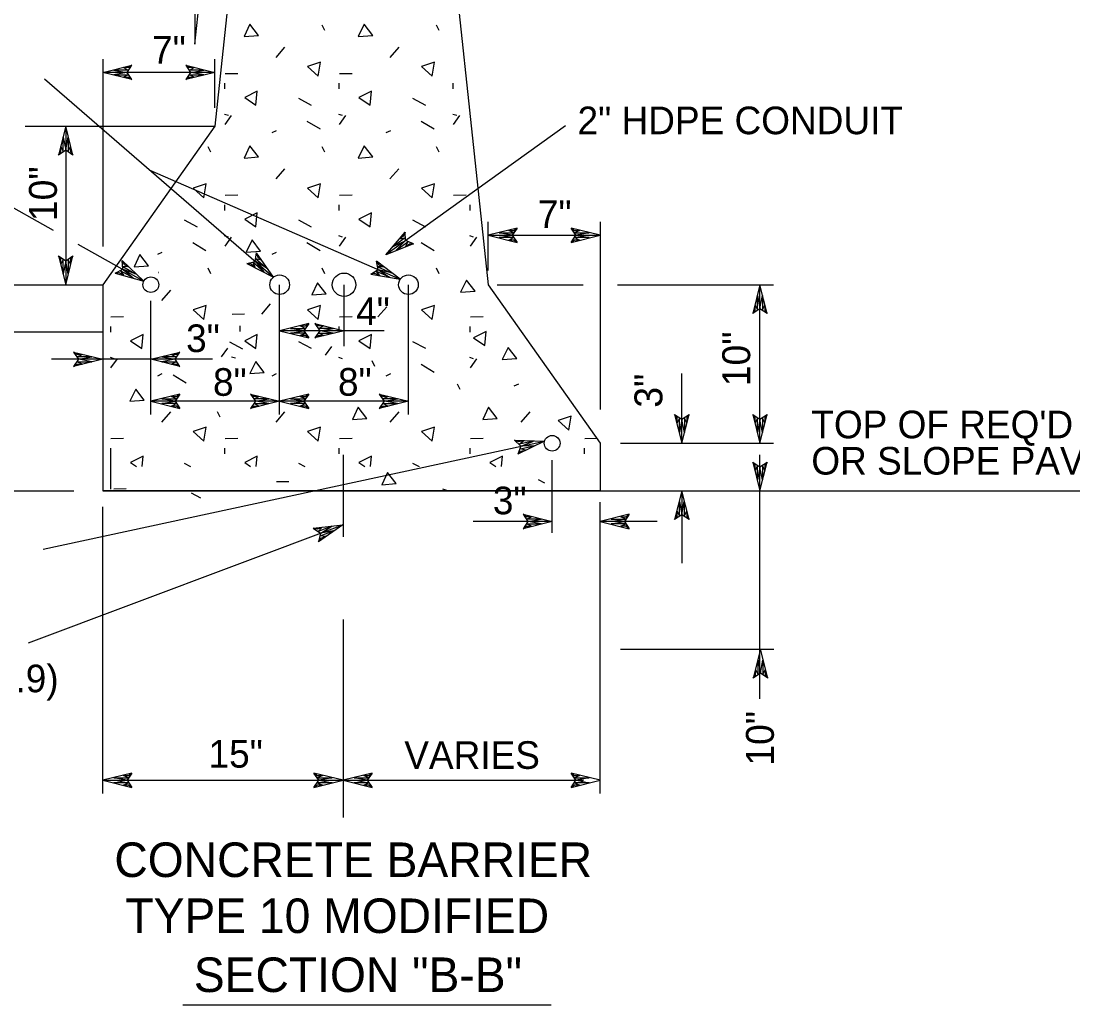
# Model space of a CAD drawing. Extents: x 504255 to 505955, y 659986 to 661086.
# Drawn here: x 504800.9 to 505019.2, y 660598.4 to 660802.7 of the extents above; entities that cross this region are included whole.
import ezdxf

# ---------------------------------------------------------------- set-up
doc = ezdxf.new("R2010")
doc.units = 0
for name, color, linetype in [('Level1', 7, 'Continuous'), ('Level3', 7, 'Continuous'), ('Level63', 7, 'Continuous')]:
    doc.layers.add(name, color=color, linetype=linetype)

msp = doc.modelspace()

# ---------------------------------------------------------------- linework, layer by layer
at = {"layer": 'Level1'}
for p, q in [((504836.94, 660797.95), (504841, 660836.25)), ((504836.94, 660836.25), (504836.94, 660797.95)), ((504817.81, 660794.84), (504817.81, 660755.89)), ((504841.09, 660784.74), (504841.09, 660794.84)), ((504841.09, 660792.07), (504817.81, 660792.07)), ((504805.69, 660790.75), (504853.25, 660749.56)), ((504801.72, 660780.9), (504841.09, 660780.9)), ((504810.12, 660780.9), (504810.12, 660747.99)), ((504913.88, 660780.98), (504876.56, 660754.22)), ((504827.59, 660771.79), (504879.56, 660749.11)), ((504792.67, 660767.62), (504807.54, 660759.29)), ((504897.78, 660750.93), (504897.78, 660761.02)), ((504921.05, 660761.02), (504921.05, 660722.07)), ((504812.63, 660756.44), (504826.35, 660748.74)), ((504897.78, 660758.26), (504921.05, 660758.26)), ((504795.68, 660747.99), (504817.81, 660747.99)), ((504854.52, 660721.03), (504854.52, 660747.99)), ((504867.88, 660735.21), (504867.88, 660747.99)), ((504881.25, 660721.03), (504881.25, 660747.99)), ((504899.7, 660747.99), (504917.49, 660747.99)), ((504924.66, 660747.99), (504957, 660747.99)), ((504954.2, 660715.08), (504954.2, 660747.99)), ((504827.79, 660721.03), (504827.79, 660744.66)), ((504876.24, 660738.42), (504854.52, 660738.42)), ((504840.61, 660732.51), (504807.19, 660732.51)), ((504938.01, 660715.08), (504938.01, 660729.53)), ((504854.52, 660723.79), (504827.79, 660723.79)), ((504881.25, 660723.79), (504854.52, 660723.79)), ((504805.43, 660693.05), (504909.51, 660715.51)), ((504925.29, 660715.08), (504957, 660715.08)), ((504867.68, 660712.65), (504867.68, 660695.64)), ((504911.08, 660696.5), (504911.08, 660711.53)), ((504954.2, 660662), (504954.2, 660712.65)), ((504768.57, 660705.2), (504811.82, 660705.2)), ((504938.01, 660705.2), (504938.01, 660690.18)), ((504817.81, 660642.32), (504817.81, 660701.86)), ((504921.05, 660642.32), (504921.05, 660702.87)), ((504802.41, 660673.61), (504867.67, 660698.15)), ((504911.08, 660698.82), (504894.72, 660698.82)), ((504932.88, 660698.82), (504921.05, 660698.82)), ((504867.69, 660678.46), (504867.69, 660637.37)), ((504925.29, 660672.29), (504957.1, 660672.29)), ((504817.81, 660645.08), (504867.69, 660645.08)), ((504867.69, 660645.08), (504917.56, 660645.08)), ((504834.41, 660598.43), (504910.91, 660598.43))]:
    msp.add_line(p, q, dxfattribs=at)
for points in [[(504847.43, 660840.63), (504841.09, 660780.9)], [(504887.94, 660840.63), (504897.78, 660747.99)], [(504823.85, 660790.58), (504817.81, 660792.07), (504823.85, 660793.57), (504823.14, 660793.07), (504822.09, 660793.07), (504823.1, 660792.57), (504820.08, 660792.57), (504822.77, 660792.07), (504820.08, 660791.57), (504823.1, 660791.57), (504822.09, 660791.08), (504823.14, 660791.08), (504823.85, 660790.58), (504822.85, 660792.07), (504823.85, 660793.57)], [(504835.04, 660793.57), (504841.09, 660792.07), (504835.04, 660790.58), (504835.76, 660791.08), (504836.8, 660791.08), (504835.79, 660791.57), (504838.81, 660791.57), (504836.13, 660792.07), (504838.81, 660792.57), (504835.79, 660792.57), (504836.8, 660793.07), (504835.76, 660793.07), (504835.04, 660793.57), (504836.05, 660792.07), (504835.04, 660790.58)], [(504811.63, 660774.92), (504810.12, 660780.9), (504808.61, 660774.92), (504809.12, 660775.63), (504809.12, 660776.67), (504809.62, 660775.67), (504809.62, 660778.66), (504810.12, 660776), (504810.62, 660778.66), (504810.62, 660775.67), (504811.13, 660776.67), (504811.13, 660775.63), (504811.63, 660774.92), (504810.12, 660775.92), (504808.61, 660774.92)], [(504841.09, 660780.9), (504817.81, 660747.99)], [(504882.32, 660756.51), (504876.56, 660754.22), (504880.56, 660758.93), (504880.27, 660758.11), (504879.43, 660757.51), (504880.55, 660757.69), (504878.1, 660755.93), (504880.57, 660757.1), (504878.68, 660755.13), (504881.14, 660756.89), (504880.61, 660755.89), (504881.45, 660756.51), (504882.32, 660756.51), (504880.63, 660757.14), (504880.56, 660758.93)], [(504903.82, 660759.75), (504897.78, 660758.26), (504903.82, 660756.77), (504903.11, 660757.26), (504902.06, 660757.26), (504903.07, 660757.76), (504900.05, 660757.76), (504902.74, 660758.26), (504900.05, 660758.75), (504903.07, 660758.75), (504902.06, 660759.26), (504903.11, 660759.26), (504903.82, 660759.75), (504902.81, 660758.26), (504903.82, 660756.77)], [(504915.02, 660756.77), (504921.05, 660758.26), (504915.02, 660759.75), (504915.73, 660759.26), (504916.77, 660759.26), (504915.76, 660758.75), (504918.78, 660758.75), (504916.1, 660758.26), (504918.78, 660757.76), (504915.76, 660757.76), (504916.77, 660757.26), (504915.73, 660757.26), (504915.02, 660756.77), (504916.02, 660758.26), (504915.02, 660759.75)], [(504847.72, 660752.37), (504853.25, 660749.56), (504849.7, 660754.62), (504849.91, 660753.78), (504850.69, 660753.1), (504849.6, 660753.38), (504851.88, 660751.41), (504849.52, 660752.79), (504851.22, 660750.66), (504848.94, 660752.64), (504849.37, 660751.6), (504848.59, 660752.28), (504847.72, 660752.37), (504849.47, 660752.84), (504849.7, 660754.62)], [(504808.61, 660753.97), (504810.12, 660747.99), (504811.63, 660753.97), (504811.13, 660753.26), (504811.13, 660752.23), (504810.63, 660753.23), (504810.63, 660750.24), (504810.12, 660752.9), (504809.62, 660750.24), (504809.62, 660753.23), (504809.12, 660752.23), (504809.12, 660753.26), (504808.61, 660753.97), (504810.12, 660752.97), (504811.63, 660753.97)], [(504820.36, 660750.39), (504826.35, 660748.74), (504821.84, 660752.99), (504822.22, 660752.21), (504823.12, 660751.7), (504822, 660751.76), (504824.62, 660750.28), (504822.04, 660751.16), (504824.14, 660749.42), (504821.5, 660750.89), (504822.13, 660749.96), (504821.23, 660750.48), (504820.36, 660750.39), (504821.98, 660751.2), (504821.84, 660752.99)], [(504873.44, 660750.16), (504879.56, 660749.11), (504874.65, 660752.89), (504875.1, 660752.15), (504876.05, 660751.73), (504874.92, 660751.68), (504877.69, 660750.47), (504875.03, 660751.09), (504877.29, 660749.56), (504874.52, 660750.77), (504875.24, 660749.91), (504874.29, 660750.33), (504873.44, 660750.16), (504874.96, 660751.13), (504874.65, 660752.89)], [(504817.81, 660747.99), (504817.81, 660705.2)], [(504897.78, 660747.99), (504921.05, 660715.08)], [(504955.71, 660742.01), (504954.2, 660747.99), (504952.7, 660742.01), (504953.2, 660742.72), (504953.2, 660743.75), (504953.7, 660742.75), (504953.7, 660745.75), (504954.2, 660743.08), (504954.71, 660745.75), (504954.71, 660742.75), (504955.21, 660743.75), (504955.21, 660742.72), (504955.71, 660742.01), (504954.2, 660743.01), (504952.7, 660742.01)], [(504860.56, 660739.92), (504854.52, 660738.42), (504860.56, 660736.93), (504859.85, 660737.43), (504858.8, 660737.43), (504859.81, 660737.93), (504856.79, 660737.93), (504859.47, 660738.42), (504856.79, 660738.92), (504859.81, 660738.92), (504858.8, 660739.42), (504859.85, 660739.42), (504860.56, 660739.92), (504859.55, 660738.42), (504860.56, 660736.93)], [(504861.84, 660739.92), (504867.88, 660738.42), (504861.84, 660736.93), (504862.56, 660737.43), (504863.6, 660737.43), (504862.59, 660737.93), (504865.61, 660737.93), (504862.93, 660738.42), (504865.61, 660738.92), (504862.59, 660738.92), (504863.6, 660739.42), (504862.56, 660739.42), (504861.84, 660739.92), (504862.85, 660738.42), (504861.84, 660736.93)], [(504811.77, 660734), (504817.81, 660732.51), (504811.77, 660731.02), (504812.49, 660731.51), (504813.53, 660731.51), (504812.52, 660732.01), (504815.54, 660732.01), (504812.86, 660732.51), (504815.54, 660733.01), (504812.52, 660733.01), (504813.53, 660733.51), (504812.49, 660733.51), (504811.77, 660734), (504812.78, 660732.51), (504811.77, 660731.02)], [(504833.82, 660731.02), (504827.79, 660732.51), (504833.82, 660734), (504833.11, 660733.51), (504832.07, 660733.51), (504833.08, 660733.01), (504830.06, 660733.01), (504832.74, 660732.51), (504830.06, 660732.01), (504833.08, 660732.01), (504832.07, 660731.51), (504833.11, 660731.51), (504833.82, 660731.02), (504832.82, 660732.51), (504833.82, 660734)], [(504833.83, 660725.29), (504827.79, 660723.79), (504833.83, 660722.3), (504833.11, 660722.8), (504832.07, 660722.8), (504833.08, 660723.3), (504830.06, 660723.3), (504832.74, 660723.79), (504830.06, 660724.29), (504833.08, 660724.29), (504832.07, 660724.79), (504833.11, 660724.79), (504833.83, 660725.29), (504832.82, 660723.79), (504833.83, 660722.3)], [(504848.48, 660725.29), (504854.52, 660723.79), (504848.48, 660722.3), (504849.19, 660722.8), (504850.23, 660722.8), (504849.23, 660723.3), (504852.25, 660723.3), (504849.57, 660723.79), (504852.25, 660724.29), (504849.23, 660724.29), (504850.23, 660724.79), (504849.19, 660724.79), (504848.48, 660725.29), (504849.49, 660723.79), (504848.48, 660722.3)], [(504860.56, 660725.29), (504854.52, 660723.79), (504860.56, 660722.3), (504859.85, 660722.8), (504858.8, 660722.8), (504859.81, 660723.3), (504856.79, 660723.3), (504859.47, 660723.79), (504856.79, 660724.29), (504859.81, 660724.29), (504858.8, 660724.79), (504859.85, 660724.79), (504860.56, 660725.29), (504859.55, 660723.79), (504860.56, 660722.3)], [(504875.21, 660725.29), (504881.25, 660723.79), (504875.21, 660722.3), (504875.92, 660722.8), (504876.97, 660722.8), (504875.96, 660723.3), (504878.98, 660723.3), (504876.3, 660723.79), (504878.98, 660724.29), (504875.96, 660724.29), (504876.97, 660724.79), (504875.92, 660724.79), (504875.21, 660725.29), (504876.22, 660723.79), (504875.21, 660722.3)], [(504936.5, 660721.05), (504938.01, 660715.08), (504939.52, 660721.05), (504939.02, 660720.35), (504939.02, 660719.32), (504938.52, 660720.31), (504938.52, 660717.33), (504938.01, 660719.98), (504937.51, 660717.33), (504937.51, 660720.31), (504937.01, 660719.32), (504937.01, 660720.35), (504936.5, 660721.05), (504938.01, 660720.06), (504939.52, 660721.05)], [(504952.7, 660721.04), (504954.2, 660715.08), (504955.71, 660721.04), (504955.21, 660720.34), (504955.21, 660719.31), (504954.71, 660720.31), (504954.71, 660717.32), (504954.2, 660719.98), (504953.7, 660717.32), (504953.7, 660720.31), (504953.2, 660719.31), (504953.2, 660720.34), (504952.7, 660721.04), (504954.2, 660720.05), (504955.71, 660721.04)], [(504903.3, 660715.7), (504909.51, 660715.51), (504903.94, 660712.78), (504904.53, 660713.42), (504905.54, 660713.64), (504904.45, 660713.91), (504907.4, 660714.56), (504904.67, 660714.47), (504907.19, 660715.52), (504904.24, 660714.88), (504905.12, 660715.59), (504904.1, 660715.36), (504903.3, 660715.7), (504904.6, 660714.45), (504903.94, 660712.78)], [(504921.05, 660715.08), (504921.05, 660705.2)], [(504952.7, 660711.17), (504954.2, 660705.2), (504955.71, 660711.17), (504955.21, 660710.47), (504955.21, 660709.44), (504954.71, 660710.44), (504954.71, 660707.45), (504954.2, 660710.11), (504953.7, 660707.45), (504953.7, 660710.44), (504953.2, 660709.44), (504953.2, 660710.47), (504952.7, 660711.17), (504954.2, 660710.18), (504955.71, 660711.17)], [(504921.05, 660705.2), (504817.81, 660705.2)], [(504939.52, 660699.23), (504938.01, 660705.2), (504936.5, 660699.23), (504937.01, 660699.93), (504937.01, 660700.96), (504937.51, 660699.96), (504937.51, 660702.96), (504938.01, 660700.29), (504938.51, 660702.96), (504938.51, 660699.96), (504939.02, 660700.96), (504939.02, 660699.93), (504939.52, 660699.23), (504938.01, 660700.22), (504936.5, 660699.23)], [(504905.04, 660700.32), (504911.08, 660698.82), (504905.04, 660697.33), (504905.75, 660697.83), (504906.79, 660697.83), (504905.79, 660698.33), (504908.8, 660698.33), (504906.12, 660698.82), (504908.8, 660699.32), (504905.79, 660699.32), (504906.79, 660699.82), (504905.75, 660699.82), (504905.04, 660700.32), (504906.05, 660698.82), (504905.04, 660697.33)], [(504927.09, 660700.32), (504921.05, 660698.82), (504927.09, 660697.33), (504926.38, 660697.83), (504925.34, 660697.83), (504926.34, 660698.33), (504923.32, 660698.33), (504926.01, 660698.82), (504923.32, 660699.32), (504926.34, 660699.32), (504925.34, 660699.82), (504926.38, 660699.82), (504927.09, 660700.32), (504926.08, 660698.82), (504927.09, 660697.33)], [(504861.49, 660697.43), (504867.67, 660698.15), (504862.56, 660694.63), (504863.05, 660695.35), (504864.02, 660695.72), (504862.9, 660695.83), (504865.72, 660696.9), (504863.04, 660696.41), (504865.38, 660697.82), (504862.55, 660696.76), (504863.31, 660697.58), (504862.34, 660697.21), (504861.49, 660697.43), (504862.97, 660696.38), (504862.56, 660694.63)], [(504955.82, 660666.31), (504954.31, 660672.29), (504952.8, 660666.31), (504953.31, 660667.01), (504953.31, 660668.05), (504953.81, 660667.05), (504953.81, 660670.04), (504954.31, 660667.38), (504954.81, 660670.04), (504954.81, 660667.05), (504955.31, 660668.05), (504955.31, 660667.01), (504955.82, 660666.31), (504954.31, 660667.31), (504952.8, 660666.31)], [(504823.86, 660646.58), (504817.81, 660645.08), (504823.86, 660643.59), (504823.14, 660644.09), (504822.1, 660644.09), (504823.1, 660644.58), (504820.09, 660644.58), (504822.77, 660645.08), (504820.09, 660645.58), (504823.1, 660645.58), (504822.1, 660646.08), (504823.14, 660646.08), (504823.86, 660646.58), (504822.85, 660645.08), (504823.86, 660643.59)], [(504861.65, 660643.59), (504867.69, 660645.08), (504861.65, 660646.58), (504862.36, 660646.08), (504863.41, 660646.08), (504862.4, 660645.58), (504865.42, 660645.58), (504862.73, 660645.08), (504865.42, 660644.58), (504862.4, 660644.58), (504863.41, 660644.09), (504862.36, 660644.09), (504861.65, 660643.59), (504862.65, 660645.08), (504861.65, 660646.58)], [(504873.73, 660646.58), (504867.69, 660645.08), (504873.73, 660643.59), (504873.01, 660644.09), (504871.97, 660644.09), (504872.98, 660644.58), (504869.96, 660644.58), (504872.64, 660645.08), (504869.96, 660645.58), (504872.98, 660645.58), (504871.97, 660646.08), (504873.01, 660646.08), (504873.73, 660646.58), (504872.72, 660645.08), (504873.73, 660643.59)], [(504915.02, 660643.59), (504921.05, 660645.08), (504915.02, 660646.58), (504915.73, 660646.08), (504916.77, 660646.08), (504915.76, 660645.58), (504918.78, 660645.58), (504916.1, 660645.08), (504918.78, 660644.58), (504915.76, 660644.58), (504916.77, 660644.09), (504915.73, 660644.09), (504915.02, 660643.59), (504916.02, 660645.08), (504915.02, 660646.58)]]:
    msp.add_lwpolyline(points, dxfattribs=at)
for points in [[(504829.34, 660750.54), (504829.34, 660750.54), (504829.35, 660750.54)], [(505010.52, 660705.2), (505010.52, 660705.2), (505010.52, 660705.2)]]:
    msp.add_lwpolyline(points, close=True, dxfattribs=at)
at = {"layer": 'Level3'}
for p, q in [((504863.29, 660801.98), (504863.84, 660800.83)), ((504886.98, 660801.98), (504887.54, 660800.83)), ((504855.55, 660797.34), (504853.71, 660795.2)), ((504879.25, 660797.34), (504877.42, 660795.2)), ((504845.84, 660791.8), (504843.22, 660791.75)), ((504869.54, 660791.8), (504866.93, 660791.75)), ((504843.09, 660789.81), (504843.09, 660788.63)), ((504866.8, 660789.81), (504866.8, 660788.63)), ((504890.49, 660789.81), (504890.49, 660788.63)), ((504858.43, 660786.69), (504861.08, 660785.28)), ((504882.13, 660786.69), (504884.78, 660785.28)), ((504843.88, 660783.13), (504843.09, 660783.36)), ((504844.47, 660783.13), (504843.15, 660781.27)), ((504867.58, 660783.13), (504866.8, 660783.36)), ((504868.17, 660783.13), (504866.85, 660781.27)), ((504891.29, 660783.13), (504890.49, 660783.36)), ((504891.88, 660783.13), (504890.56, 660781.27)), ((504860.18, 660781.97), (504862.92, 660780.36)), ((504883.88, 660781.97), (504886.62, 660780.36)), ((504852.94, 660779.6), (504853.88, 660780.04)), ((504876.64, 660779.6), (504877.58, 660780.04)), ((504839.59, 660776.72), (504840.14, 660775.58)), ((504863.29, 660776.72), (504863.84, 660775.58)), ((504886.98, 660776.72), (504887.54, 660775.58)), ((504855.55, 660772.08), (504853.71, 660769.96)), ((504879.25, 660772.08), (504877.42, 660769.96)), ((504845.84, 660766.55), (504843.22, 660766.49)), ((504869.54, 660766.55), (504866.93, 660766.49)), ((504893.24, 660766.55), (504890.62, 660766.49)), ((504843.09, 660764.56), (504843.09, 660763.38)), ((504866.8, 660764.56), (504866.8, 660763.38)), ((504893.99, 660764.56), (504893.99, 660763.38)), ((504834.73, 660761.45), (504837.38, 660760.04)), ((504858.43, 660761.45), (504861.08, 660760.04)), ((504882.13, 660761.45), (504884.78, 660760.04)), ((504836.48, 660756.72), (504839.23, 660755.11)), ((504843.88, 660757.88), (504843.09, 660758.11)), ((504844.47, 660757.88), (504843.15, 660756.02)), ((504860.18, 660756.72), (504862.92, 660755.11)), ((504867.58, 660757.88), (504866.8, 660758.11)), ((504868.17, 660757.88), (504866.85, 660756.02)), ((504883.88, 660756.72), (504886.62, 660755.11)), ((504894.78, 660757.88), (504893.99, 660758.11)), ((504895.37, 660757.88), (504894.05, 660756.02)), ((504829.24, 660754.35), (504830.17, 660754.78)), ((504852.94, 660754.35), (504853.88, 660754.78)), ((504876.64, 660754.35), (504877.58, 660754.78)), ((504839.59, 660751.47), (504840.14, 660750.32)), ((504863.29, 660751.47), (504863.84, 660750.32)), ((504886.98, 660751.47), (504887.54, 660750.32)), ((504831.85, 660746.83), (504830.02, 660744.7)), ((504852.59, 660744.01), (504850.75, 660741.88)), ((504876.76, 660743.42), (504874.93, 660741.29)), ((504822.14, 660741.3), (504819.52, 660741.24)), ((504847.26, 660741.88), (504844.64, 660741.82)), ((504869.54, 660741.3), (504866.93, 660741.24)), ((504896.74, 660741.3), (504894.12, 660741.24)), ((504819.39, 660739.31), (504819.39, 660738.13)), ((504846.26, 660739.48), (504846.26, 660738.29)), ((504866.8, 660739.31), (504866.8, 660738.13)), ((504893.99, 660739.31), (504893.99, 660738.13)), ((504843.69, 660734.84), (504842.37, 660732.98)), ((504844.15, 660736.11), (504846.8, 660734.7)), ((504858.43, 660736.19), (504861.08, 660734.78)), ((504865.29, 660735.18), (504863.96, 660733.33)), ((504882.13, 660736.19), (504884.78, 660734.78)), ((504820.18, 660732.62), (504819.39, 660732.86)), ((504820.78, 660732.62), (504819.45, 660730.76)), ((504845.34, 660732.73), (504844.54, 660732.97)), ((504867.58, 660732.62), (504866.8, 660732.86)), ((504894.78, 660732.62), (504893.99, 660732.86)), ((504895.37, 660732.62), (504894.05, 660730.76)), ((504873.63, 660732.24), (504874.19, 660731.09)), ((504883.88, 660731.46), (504886.62, 660729.85)), ((504829.24, 660729.09), (504830.17, 660729.53)), ((504832.39, 660729.25), (504835.13, 660727.64)), ((504852.94, 660729.09), (504853.88, 660729.53)), ((504876.64, 660729.09), (504877.58, 660729.53)), ((504891.39, 660727.42), (504891.95, 660726.28)), ((504903.23, 660726.98), (504904.17, 660727.42)), ((504831.85, 660721.57), (504830.02, 660719.45)), ((504841.57, 660721.69), (504842.12, 660720.54)), ((504855.55, 660721.57), (504853.71, 660719.45)), ((504879.25, 660721.57), (504877.42, 660719.45)), ((504906.44, 660721.57), (504904.61, 660719.45)), ((504822.14, 660716.05), (504819.52, 660715.99)), ((504845.84, 660716.05), (504843.22, 660715.99)), ((504869.54, 660716.05), (504866.93, 660715.99)), ((504896.74, 660716.05), (504894.12, 660715.99)), ((504920.44, 660716.05), (504917.83, 660715.99)), ((504819.39, 660714.06), (504819.39, 660705.54)), ((504843.09, 660714.06), (504843.09, 660712.87)), ((504866.8, 660714.06), (504866.8, 660712.87)), ((504893.99, 660714.06), (504893.99, 660712.87)), ((504917.69, 660714.06), (504917.69, 660712.87)), ((504834.73, 660710.93), (504836.04, 660710.24)), ((504858.43, 660710.93), (504859.75, 660710.24)), ((504882.13, 660710.93), (504883.45, 660710.24)), ((504856.46, 660707.09), (504853.85, 660707.04)), ((504908.18, 660707.53), (504909.5, 660706.83)), ((504822.69, 660705.62), (504820.08, 660705.55)), ((504836.18, 660704.78), (504838.09, 660703.76)), ((504889.21, 660705.29), (504888.42, 660705.53))]:
    msp.add_line(p, q, dxfattribs=at)
for points in [[(504848.35, 660802.09), (504847.16, 660799.55), (504850.13, 660799.76)], [(504872.04, 660802.09), (504870.85, 660799.55), (504873.83, 660799.76)], [(504862.97, 660794.17), (504860.29, 660793.27), (504862.5, 660791.29)], [(504886.67, 660794.17), (504883.99, 660793.27), (504886.2, 660791.29)], [(504847.27, 660786.83), (504849.59, 660785.25), (504849.88, 660788.18)], [(504870.97, 660786.83), (504873.3, 660785.25), (504873.58, 660788.18)], [(504848.35, 660776.83), (504847.16, 660774.29), (504850.13, 660774.51)], [(504872.04, 660776.83), (504870.85, 660774.29), (504873.83, 660774.51)], [(504839.27, 660768.91), (504836.59, 660768.01), (504838.8, 660766.03)], [(504862.97, 660768.91), (504860.29, 660768.01), (504862.5, 660766.03)], [(504886.67, 660768.91), (504883.99, 660768.01), (504886.2, 660766.03)], [(504847.27, 660761.59), (504849.59, 660759.99), (504849.88, 660762.92)], [(504870.97, 660761.59), (504873.3, 660759.99), (504873.58, 660762.92)], [(504848.79, 660757.29), (504847.6, 660754.75), (504850.57, 660754.97)], [(504825.5, 660754.23), (504824.31, 660751.69), (504827.29, 660751.91)], [(504862.41, 660748.41), (504861.22, 660745.87), (504864.2, 660746.09)], [(504893.29, 660748.96), (504892.09, 660746.42), (504895.07, 660746.64)], [(504839.27, 660743.66), (504836.59, 660742.76), (504838.8, 660740.78)], [(504862.97, 660743.66), (504860.29, 660742.76), (504862.5, 660740.78)], [(504886.67, 660743.66), (504883.99, 660742.76), (504886.2, 660740.78)], [(504823.57, 660736.32), (504825.89, 660734.74), (504826.18, 660737.67)], [(504847.27, 660736.32), (504849.59, 660734.74), (504849.88, 660737.67)], [(504870.97, 660736.32), (504873.3, 660734.74), (504873.58, 660737.67)], [(504894.76, 660736.94), (504897.09, 660735.35), (504897.37, 660738.29)], [(504901.93, 660734.97), (504900.74, 660732.43), (504903.72, 660732.65)], [(504849.57, 660732.06), (504848.37, 660729.52), (504851.34, 660729.74)], [(504824.65, 660726.33), (504823.45, 660723.78), (504826.43, 660724)], [(504870.83, 660722.56), (504869.64, 660720.01), (504872.61, 660720.23)], [(504897.87, 660722.55), (504896.68, 660720.01), (504899.65, 660720.23)], [(504915.01, 660720.68), (504912.33, 660719.78), (504914.54, 660717.8)], [(504839.27, 660718.4), (504836.59, 660717.51), (504838.8, 660715.53)], [(504862.97, 660718.4), (504860.29, 660717.51), (504862.5, 660715.53)], [(504886.67, 660718.4), (504883.99, 660717.51), (504886.2, 660715.53)], [(504876.91, 660709), (504875.72, 660706.46), (504878.69, 660706.69)]]:
    msp.add_lwpolyline(points, close=True, dxfattribs=at)
for points in [[(504825.97, 660710.24), (504826.18, 660712.42), (504823.57, 660711.08), (504824.79, 660710.24)], [(504849.67, 660710.24), (504849.88, 660712.42), (504847.27, 660711.08), (504848.5, 660710.24)], [(504873.37, 660710.24), (504873.58, 660712.42), (504870.97, 660711.08), (504872.2, 660710.24)], [(504900.57, 660710.24), (504900.78, 660712.42), (504898.17, 660711.08), (504899.4, 660710.24)]]:
    msp.add_lwpolyline(points, dxfattribs=at)
at = {"layer": 'Level63'}
for p, q in [((504817.81, 660738.11), (504625.17, 660738.11)), ((504849.7, 660710.24), (504849.7, 660710.24)), ((504921.05, 660710.24), (504921.05, 660710.24)), ((504817.81, 660705.2), (505079.25, 660705.2))]:
    msp.add_line(p, q, dxfattribs=at)
for centre, major_axis in [((504854.52, 660747.99), (-2.04, 0)), ((504867.89, 660747.99), (-2.44, 0)), ((504881.25, 660747.99), (-2.04, 0)), ((504827.79, 660747.99), (-1.63, 0)), ((504911.08, 660715.07), (1.63, 0))]:
    msp.add_ellipse(centre, major_axis=major_axis, ratio=0.99, dxfattribs=at)

# ---------------------------------------------------------------- texts
at = {"layer": 'Level1'}
for s, height, p in [('7"', 5.739, (504828.05, 660793.88)), ('2" HDPE CONDUIT', 5.7392, (504916.35, 660779.24)), ('7"', 5.739, (504908.12, 660759.79)), ('4"', 5.739, (504870.39, 660739.61)), ('3"', 5.739, (504835.11, 660734)), ('8"', 5.739, (504840.69, 660724.92)), ('8"', 5.739, (504866.63, 660724.94)), ("TOP OF REQ'D PAVING ", 5.7392, (504964.87, 660716.1)), ('OR SLOPE PAVING', 5.7392, (504964.87, 660708.56)), ('3"', 5.739, (504898.78, 660700.32)), ('(SEE NOTE NO.9)', 5.7392, (504744.69, 660663.36)), ('15"', 5.739, (504839.77, 660647.71)), ('VARIES', 5.739, (504880.39, 660647.46)), ('CONCRETE BARRIER', 7.1744, (504820.22, 660625)), ('TYPE 10 MODIFIED', 7.173, (504822.51, 660613.37)), ('SECTION "B-B"', 7.1744, (504836.71, 660601.12))]:
    msp.add_text(s, height=height, dxfattribs=at).set_placement(p)
for s, p in [('10"', (504808.3, 660761.19)), ('10"', (504952.18, 660726.9)), ('3"', (504933.96, 660722.45)), ('10"', (504957.1, 660648.11))]:
    msp.add_text(s, height=5.797, rotation=90, dxfattribs=at).set_placement(p)

doc.saveas('drawing.dxf')
